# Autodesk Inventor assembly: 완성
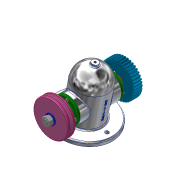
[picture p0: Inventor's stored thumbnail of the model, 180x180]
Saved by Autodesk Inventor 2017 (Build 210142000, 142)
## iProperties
Created: 2019-11
Part Number: 완성
Document SubType Name: Assembly
Designer: 1-08-lg
Author: 1-08-lg
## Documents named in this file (14)
- C:\Users\1-08-lg\Desktop\완성.iam
- C:\Users\1-08-lg\Desktop\본체.ipt
- C:\Users\1-08-lg\Desktop\491104V1010\볼트 M4.ipt
- C:\Users\1-08-lg\Desktop\491104V1010\부시.ipt
- C:\Users\1-08-lg\Desktop\491104V1010\스퍼기어.ipt
- C:\Users\1-08-lg\Desktop\491104V1010\오일 실 26 38 8.ipt
- C:\Users\1-08-lg\Desktop\491104V1010\와셔 12x24.ipt
- C:\Users\1-08-lg\Desktop\491104V1010\축.ipt
- C:\Users\1-08-lg\Desktop\491104V1010\커버.ipt
- C:\Users\1-08-lg\Desktop\491104V1010\키 5x5x12.ipt
- C:\Users\1-08-lg\Desktop\491104V1010\V-벨트풀리.ipt
- V-벨트풀리.ipt
- C:\Users\1-08-lg\Desktop\491104V1010\너트 M12x1.25.ipt
- C:\Users\1-08-lg\Desktop\491104V1010\베어링 6203.ipt
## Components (1 placed, 1 different names)
1. V-벨트풀리:1 — Mate:37, Mate:38, Mate:54, Mate:63
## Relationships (4: Mate 4)
- Mate:37: V-벨트풀리:1
- Mate:38: V-벨트풀리:1
- Mate:54: V-벨트풀리:1
- Mate:63: V-벨트풀리:1
